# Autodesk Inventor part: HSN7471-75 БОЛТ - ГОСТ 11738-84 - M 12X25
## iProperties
Created: 2011-02
Part Number: HSN7471-75 БОЛТ - ГОСТ 11738-84 - M 12X25
Document SubType Name: Modeling
Designer: Чернышев Юрий
Mass: 5.2057 g
Surface Area: 23.5989 cm^2
Volume: 5.2057 cm^3
Density: 1 g/cm^3
Author: Чернышев Юрий
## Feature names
1. Base1
